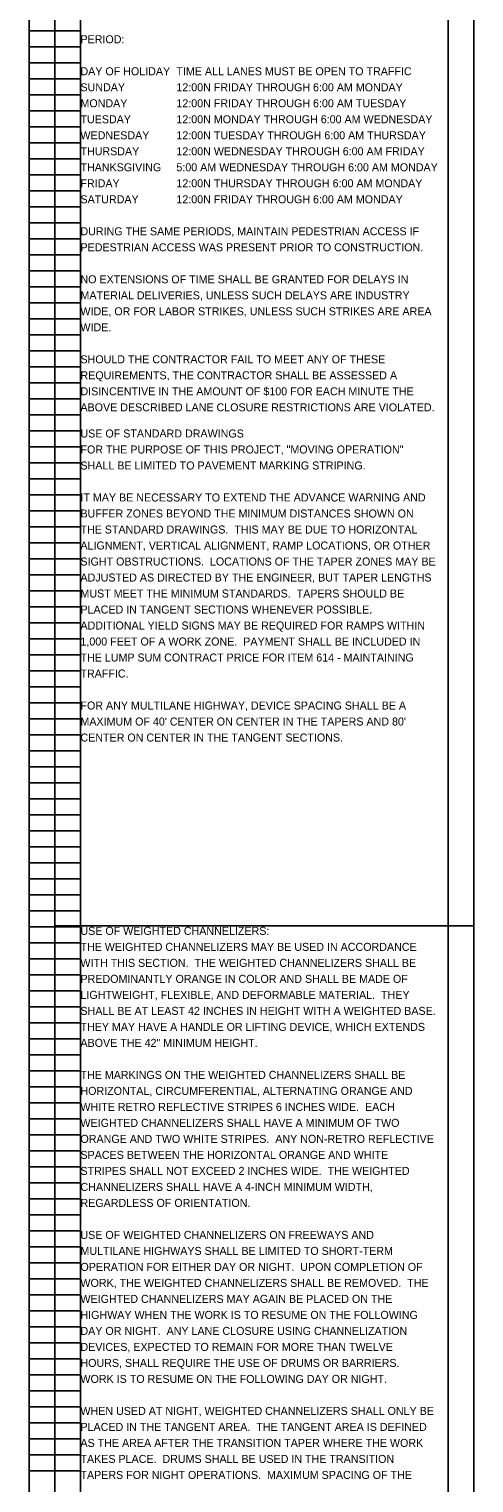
# Model space of a CAD drawing. Extents: x -13 to 29, y -301 to 22.
# Drawn here: x 1.5 to 9.29, y -28.91 to -3.47 of the extents above; entities that cross this region are included whole.
import ezdxf

# ---------------------------------------------------------------- set-up
doc = ezdxf.new("R2010")
doc.units = 0
doc.layers.add('SC_Scratch1', color=7, linetype='Continuous')
doc.layers.add('SH_Text', color=7, linetype='Continuous')

msp = doc.modelspace()

# ---------------------------------------------------------------- linework, layer by layer
at = {"layer": 'SH_Text'}
for p, q in [((1.5, -19.18), (1.5, 0.98)), ((2.4, -19.18), (2.4, 0.98)), ((8.84, -19.18), (8.84, 0.98)), ((1.5, -3.5), (2.4, -3.5)), ((1.5, -3.78), (2.4, -3.78)), ((1.5, -4.06), (2.4, -4.06)), ((1.5, -4.34), (2.4, -4.34)), ((1.5, -4.62), (2.4, -4.62)), ((1.5, -4.9), (2.4, -4.9)), ((1.5, -5.18), (2.4, -5.18)), ((1.5, -5.46), (2.4, -5.46)), ((1.5, -5.74), (2.4, -5.74)), ((1.5, -6.02), (2.4, -6.02)), ((1.5, -6.3), (2.4, -6.3)), ((1.5, -6.58), (2.4, -6.58)), ((1.5, -6.86), (2.4, -6.86)), ((1.5, -7.14), (2.4, -7.14)), ((1.5, -7.42), (2.4, -7.42)), ((1.5, -7.7), (2.4, -7.7)), ((1.5, -7.98), (2.4, -7.98)), ((1.5, -8.26), (2.4, -8.26)), ((1.5, -8.54), (2.4, -8.54)), ((1.5, -8.82), (2.4, -8.82)), ((1.5, -9.1), (2.4, -9.1)), ((1.5, -9.38), (2.4, -9.38)), ((1.5, -9.66), (2.4, -9.66)), ((1.5, -9.94), (2.4, -9.94)), ((1.5, -10.22), (2.4, -10.22)), ((1.5, -10.5), (2.4, -10.5)), ((1.5, -10.78), (2.4, -10.78)), ((1.5, -11.06), (2.4, -11.06)), ((1.5, -11.34), (2.4, -11.34)), ((1.5, -11.62), (2.4, -11.62)), ((1.5, -11.9), (2.4, -11.9)), ((1.5, -12.18), (2.4, -12.18)), ((1.5, -12.46), (2.4, -12.46)), ((1.5, -12.74), (2.4, -12.74)), ((1.5, -13.02), (2.4, -13.02)), ((1.5, -13.3), (2.4, -13.3)), ((1.5, -13.58), (2.4, -13.58)), ((1.5, -13.86), (2.4, -13.86)), ((1.5, -14.14), (2.4, -14.14)), ((1.5, -14.42), (2.4, -14.42)), ((1.5, -14.7), (2.4, -14.7)), ((1.5, -14.98), (2.4, -14.98)), ((1.5, -15.26), (2.4, -15.26)), ((1.5, -15.54), (2.4, -15.54)), ((1.5, -15.82), (2.4, -15.82)), ((1.5, -16.1), (2.4, -16.1)), ((1.5, -16.38), (2.4, -16.38)), ((1.5, -16.66), (2.4, -16.66)), ((1.5, -16.94), (2.4, -16.94)), ((1.5, -17.22), (2.4, -17.22)), ((1.5, -17.5), (2.4, -17.5)), ((1.5, -17.78), (2.4, -17.78)), ((1.5, -18.06), (2.4, -18.06)), ((1.5, -18.34), (2.4, -18.34)), ((1.5, -18.62), (2.4, -18.62)), ((1.5, -18.9), (2.4, -18.9)), ((1.5, -19.18), (2.4, -19.18)), ((1.5, -19.18), (2.4, -19.18)), ((1.5, -39.34), (1.5, -19.18)), ((2.4, -39.34), (2.4, -19.18)), ((8.84, -39.34), (8.84, -19.18)), ((1.5, -19.46), (2.4, -19.46)), ((1.5, -19.74), (2.4, -19.74)), ((1.5, -20.02), (2.4, -20.02)), ((1.5, -20.3), (2.4, -20.3)), ((1.5, -20.58), (2.4, -20.58)), ((1.5, -20.86), (2.4, -20.86)), ((1.5, -21.14), (2.4, -21.14)), ((1.5, -21.42), (2.4, -21.42)), ((1.5, -21.7), (2.4, -21.7)), ((1.5, -21.98), (2.4, -21.98)), ((1.5, -22.26), (2.4, -22.26)), ((1.5, -22.54), (2.4, -22.54)), ((1.5, -22.82), (2.4, -22.82)), ((1.5, -23.1), (2.4, -23.1)), ((1.5, -23.38), (2.4, -23.38)), ((1.5, -23.66), (2.4, -23.66)), ((1.5, -23.94), (2.4, -23.94)), ((1.5, -24.22), (2.4, -24.22)), ((1.5, -24.5), (2.4, -24.5)), ((1.5, -24.78), (2.4, -24.78)), ((1.5, -25.06), (2.4, -25.06)), ((1.5, -25.34), (2.4, -25.34)), ((1.5, -25.62), (2.4, -25.62)), ((1.5, -25.9), (2.4, -25.9)), ((1.5, -26.18), (2.4, -26.18)), ((1.5, -26.46), (2.4, -26.46)), ((1.5, -26.74), (2.4, -26.74)), ((1.5, -27.02), (2.4, -27.02)), ((1.5, -27.3), (2.4, -27.3)), ((1.5, -27.58), (2.4, -27.58)), ((1.5, -27.86), (2.4, -27.86)), ((1.5, -28.14), (2.4, -28.14)), ((1.5, -28.42), (2.4, -28.42)), ((1.5, -28.7), (2.4, -28.7))]:
    msp.add_line(p, q, dxfattribs=at)
for points in [[(1.95, 0.997), (9.29, 0.997), (9.29, -19.163), (1.95, -19.163)], [(1.95, -19.163), (9.29, -19.163), (9.29, -39.323), (1.95, -39.323)]]:
    msp.add_lwpolyline(points, close=True, dxfattribs=at)

# ---------------------------------------------------------------- texts
at = {"layer": 'SC_Scratch1'}
for s, p in [('PERIOD:', (2.4, -3.719)), ('DAY OF HOLIDAY', (2.4, -4.279)), ('TIME ALL LANES MUST BE OPEN TO TRAFFIC', (4.08, -4.279)), ('SUNDAY', (2.4, -4.559)), ('12:00N FRIDAY THROUGH 6:00 AM MONDAY', (4.08, -4.559)), ('MONDAY', (2.4, -4.839)), ('12:00N FRIDAY THROUGH 6:00 AM TUESDAY', (4.08, -4.839)), ('TUESDAY', (2.4, -5.119)), ('12:00N MONDAY THROUGH 6:00 AM WEDNESDAY', (4.08, -5.119)), ('WEDNESDAY', (2.4, -5.399)), ('12:00N TUESDAY THROUGH 6:00 AM THURSDAY', (4.08, -5.399)), ('THURSDAY', (2.4, -5.679)), ('12:00N WEDNESDAY THROUGH 6:00 AM FRIDAY', (4.08, -5.679)), ('THANKSGIVING', (2.4, -5.959)), ('5:00 AM WEDNESDAY THROUGH 6:00 AM MONDAY', (4.08, -5.959)), ('FRIDAY', (2.4, -6.239)), ('12:00N THURSDAY THROUGH 6:00 AM MONDAY', (4.08, -6.239)), ('SATURDAY', (2.4, -6.519)), ('12:00N FRIDAY THROUGH 6:00 AM MONDAY', (4.08, -6.519)), ('DURING THE SAME PERIODS, MAINTAIN PEDESTRIAN ACCESS IF ', (2.4, -7.079)), ('PEDESTRIAN ACCESS WAS PRESENT PRIOR TO CONSTRUCTION. ', (2.4, -7.359)), ('NO EXTENSIONS OF TIME SHALL BE GRANTED FOR DELAYS IN ', (2.4, -7.919)), ('MATERIAL DELIVERIES, UNLESS SUCH DELAYS ARE INDUSTRY ', (2.4, -8.199)), ('WIDE, OR FOR LABOR STRIKES, UNLESS SUCH STRIKES ARE AREA ', (2.4, -8.479)), ('WIDE.', (2.4, -8.759)), ('SHOULD THE CONTRACTOR FAIL TO MEET ANY OF THESE ', (2.4, -9.319)), ('REQUIREMENTS, THE CONTRACTOR SHALL BE ASSESSED A ', (2.4, -9.599)), ('DISINCENTIVE IN THE AMOUNT OF $100 FOR EACH MINUTE THE ', (2.4, -9.879)), ('ABOVE DESCRIBED LANE CLOSURE RESTRICTIONS ARE VIOLATED.', (2.4, -10.159)), ('USE OF STANDARD DRAWINGS', (2.4, -10.617)), ('FOR THE PURPOSE OF THIS PROJECT, "MOVING OPERATION" ', (2.4, -10.897)), ('SHALL BE LIMITED TO PAVEMENT MARKING STRIPING.', (2.4, -11.177)), ('IT MAY BE NECESSARY TO EXTEND THE ADVANCE WARNING AND ', (2.4, -11.737)), ('BUFFER ZONES BEYOND THE MINIMUM DISTANCES SHOWN ON ', (2.4, -12.017)), ('THE STANDARD DRAWINGS.  THIS MAY BE DUE TO HORIZONTAL ', (2.4, -12.297)), ('ALIGNMENT, VERTICAL ALIGNMENT, RAMP LOCATIONS, OR OTHER ', (2.4, -12.577)), ('SIGHT OBSTRUCTIONS.  LOCATIONS OF THE TAPER ZONES MAY BE ', (2.4, -12.857)), ('ADJUSTED AS DIRECTED BY THE ENGINEER, BUT TAPER LENGTHS ', (2.4, -13.137)), ('MUST MEET THE MINIMUM STANDARDS.  TAPERS SHOULD BE ', (2.4, -13.417)), ('PLACED IN TANGENT SECTIONS WHENEVER POSSIBLE.  ', (2.4, -13.697)), ('ADDITIONAL YIELD SIGNS MAY BE REQUIRED FOR RAMPS WITHIN ', (2.4, -13.977)), ('1,000 FEET OF A WORK ZONE.  PAYMENT SHALL BE INCLUDED IN ', (2.4, -14.257)), ('THE LUMP SUM CONTRACT PRICE FOR ITEM 614 - MAINTAINING ', (2.4, -14.537)), ('TRAFFIC.', (2.4, -14.817)), ('FOR ANY MULTILANE HIGHWAY, DEVICE SPACING SHALL BE A ', (2.4, -15.377)), ("MAXIMUM OF 40' CENTER ON CENTER IN THE TAPERS AND 80' ", (2.4, -15.657)), ('CENTER ON CENTER IN THE TANGENT SECTIONS.', (2.4, -15.937)), ('USE OF WEIGHTED CHANNELIZERS:', (2.4, -19.32)), ('THE WEIGHTED CHANNELIZERS MAY BE USED IN ACCORDANCE ', (2.4, -19.6)), ('WITH THIS SECTION.  THE WEIGHTED CHANNELIZERS SHALL BE ', (2.4, -19.88)), ('PREDOMINANTLY ORANGE IN COLOR AND SHALL BE MADE OF ', (2.4, -20.16)), ('LIGHTWEIGHT, FLEXIBLE, AND DEFORMABLE MATERIAL.  THEY ', (2.4, -20.44)), ('SHALL BE AT LEAST 42 INCHES IN HEIGHT WITH A WEIGHTED BASE.  ', (2.4, -20.72)), ('THEY MAY HAVE A HANDLE OR LIFTING DEVICE, WHICH EXTENDS ', (2.4, -21)), ('ABOVE THE 42" MINIMUM HEIGHT.', (2.4, -21.28)), ('THE MARKINGS ON THE WEIGHTED CHANNELIZERS SHALL BE ', (2.4, -21.84)), ('HORIZONTAL, CIRCUMFERENTIAL, ALTERNATING ORANGE AND ', (2.4, -22.12)), ('WHITE RETRO REFLECTIVE STRIPES 6 INCHES WIDE.  EACH ', (2.4, -22.4)), ('WEIGHTED CHANNELIZERS SHALL HAVE A MINIMUM OF TWO ', (2.4, -22.68)), ('ORANGE AND TWO WHITE STRIPES.  ANY NON-RETRO REFLECTIVE ', (2.4, -22.96)), ('SPACES BETWEEN THE HORIZONTAL ORANGE AND WHITE ', (2.4, -23.24)), ('STRIPES SHALL NOT EXCEED 2 INCHES WIDE.  THE WEIGHTED ', (2.4, -23.52)), ('CHANNELIZERS SHALL HAVE A 4-INCH MINIMUM WIDTH, ', (2.4, -23.8)), ('REGARDLESS OF ORIENTATION.', (2.4, -24.08)), ('USE OF WEIGHTED CHANNELIZERS ON FREEWAYS AND ', (2.4, -24.64)), ('MULTILANE HIGHWAYS SHALL BE LIMITED TO SHORT-TERM ', (2.4, -24.92)), ('OPERATION FOR EITHER DAY OR NIGHT.  UPON COMPLETION OF ', (2.4, -25.2)), ('WORK, THE WEIGHTED CHANNELIZERS SHALL BE REMOVED.  THE ', (2.4, -25.48)), ('WEIGHTED CHANNELIZERS MAY AGAIN BE PLACED ON THE ', (2.4, -25.76)), ('HIGHWAY WHEN THE WORK IS TO RESUME ON THE FOLLOWING ', (2.4, -26.04)), ('DAY OR NIGHT.  ANY LANE CLOSURE USING CHANNELIZATION ', (2.4, -26.32)), ('DEVICES, EXPECTED TO REMAIN FOR MORE THAN TWELVE ', (2.4, -26.6)), ('HOURS, SHALL REQUIRE THE USE OF DRUMS OR BARRIERS.  ', (2.4, -26.88)), ('WORK IS TO RESUME ON THE FOLLOWING DAY OR NIGHT.', (2.4, -27.16)), ('WHEN USED AT NIGHT, WEIGHTED CHANNELIZERS SHALL ONLY BE ', (2.4, -27.72)), ('PLACED IN THE TANGENT AREA.  THE TANGENT AREA IS DEFINED ', (2.4, -28)), ('AS THE AREA AFTER THE TRANSITION TAPER WHERE THE WORK ', (2.4, -28.28)), ('TAKES PLACE.  DRUMS SHALL BE USED IN THE TRANSITION ', (2.4, -28.56)), ('TAPERS FOR NIGHT OPERATIONS.  MAXIMUM SPACING OF THE ', (2.4, -28.84))]:
    msp.add_text(s, height=0.14, dxfattribs=at).set_placement(p)

doc.saveas('drawing.dxf')
